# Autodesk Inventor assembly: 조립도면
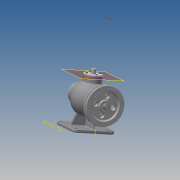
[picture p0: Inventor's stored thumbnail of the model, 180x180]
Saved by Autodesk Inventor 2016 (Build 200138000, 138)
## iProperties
Created: 2017-01
Part Number: 조립도면
Material: 일반
Document SubType Name: Assembly
Designer: Administrator
Author: Administrator
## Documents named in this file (19)
- C:\Users\Administrator\Desktop\470130V1005\조립도면.iam
- C:\Users\Administrator\Desktop\470130V1005\본체.ipt
- C:\Users\Administrator\Desktop\470130V1005\편심축.ipt
- C:\Users\Administrator\Desktop\470130V1005\멈춤링- 15 x 1.ipt
- C:\Users\Administrator\Desktop\470130V1005\멈춤링- 35x1.6.ipt
- KS B 1336 - 35x1.6.ipt
- C:\Users\Administrator\Desktop\470130V1005\부시.ipt
- C:\Users\Administrator\Desktop\470130V1005\베어링- 6202.ipt
- KS B 2023 - 6202 - 15 x 35 x 11 - 7.8.ipt
- C:\Users\Administrator\Desktop\470130V1005\키 4 x 4 x 12.ipt
- C:\Users\Administrator\Desktop\470130V1005\앞커버.ipt
- C:\Users\Administrator\Desktop\470130V1005\오일실 15 30 7.ipt
- C:\Users\Administrator\Desktop\470130V1005\V-벨트풀리.ipt
- C:\Users\Administrator\Desktop\470130V1005\너트 M8.ipt
- C:\Users\Administrator\Desktop\470130V1005\볼트 M4 x 16.ipt
- C:\Users\Administrator\Desktop\470130V1005\뒤커버.ipt
- C:\Users\Administrator\Desktop\470130V1005\슬라이드.ipt
- C:\Users\Administrator\Desktop\470130V1005\상부커버.ipt
- C:\Users\Administrator\Desktop\470130V1005\볼트 M4 x 12.ipt
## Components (17 placed, 5 different names)
1. KS B 1336 - 35x1.6:1
2. KS B 2023 - 6202 - 15 x 35 x 11 - 7.8:1
3. KS B 2023 - 6202 - 15 x 35 x 11 - 7.8:2
4. V-벨트풀리:1
5. KS B 1021 - 에 따름 ISO 1207 - 미터 A  M 4 x 12:1
6. ISO 4762 M4 x 16:1 — 플러쉬:2
7. ISO 4762 M4 x 16:2
8. ISO 4762 M4 x 16:3
9. ISO 4762 M4 x 16:4
10. ISO 4762 M4 x 16:5
11. ISO 4762 M4 x 16:6
12. ISO 4762 M4 x 16:7
13. ISO 4762 M4 x 16:8
14. KS B 1021 - 에 따름 ISO 1207 - 미터 A  M 4 x 12:2
15. KS B 1021 - 에 따름 ISO 1207 - 미터 A  M 4 x 12:3
16. KS B 1021 - 에 따름 ISO 1207 - 미터 A  M 4 x 12:4
17. KS B 1021 - 에 따름 ISO 1207 - 미터 A  M 4 x 12:5
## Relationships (1: Flush 1)
- 플러쉬:2 [Flush]: ISO 4762 M4 x 16:1
